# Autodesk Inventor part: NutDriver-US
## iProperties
Shininess: 64.0
Length Units: 11272
Angle Units: 11279
Time Units: 11290
Mass Units: 11286
Length Display Precision: 3
Angle Display Precision: 2
Compacted: True
Part Number: NutDriver-US
Document SubType Name: Modeling
Created: 2003-07
Designer: C_Hackman
Material: Steel, High Strength Low Alloy
Density: 0.0
Volumn: 0.0
Area: 0.0
PropertySet Name: Model Information
Control State: 0
Master: False
Checked Out: False
Author: C_Hackman
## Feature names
1. Shaft [Extrusion]
2. Handle, Round [Revolution]
3. Handle, Flats [Extrusion]
4. Socket [Revolution]
5. Hex, Socket [Extrusion]
